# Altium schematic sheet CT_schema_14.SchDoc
size 274 x 160 mm
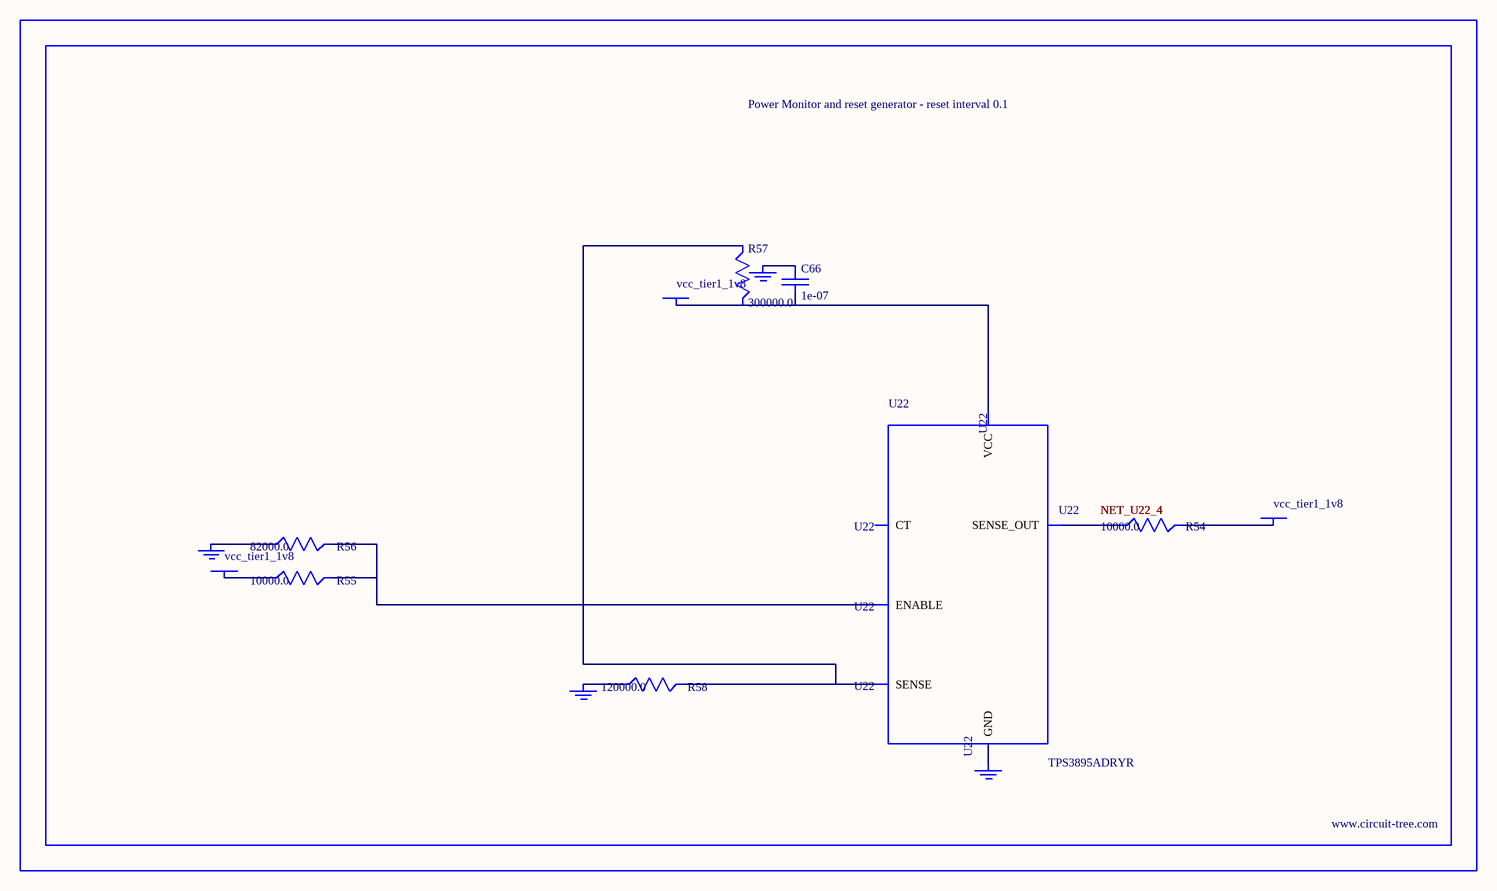
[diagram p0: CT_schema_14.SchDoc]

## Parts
BORDER13  (no value)
C66  1e-07  [C0402]
GND_INSTANCE_13_0  (no value)
GND_INSTANCE_13_1  (no value)
GND_INSTANCE_13_2  (no value)
GND_INSTANCE_13_3  (no value)
POWER_INSTANCE_13_0  vcc_tier1_1v8
POWER_INSTANCE_13_1  vcc_tier1_1v8
POWER_INSTANCE_13_2  vcc_tier1_1v8
R54  10000.0  [R0603]
R55  10000.0  [R0603]
R56  82000.0  [R0603]
R57  300000.0  [R0603]
R58  120000.0  [R0603]
U22  TPS3895ADRYR  [SON-6]

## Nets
NetC66_1: C66.1 GND_INSTANCE_13_2.0(GND)
NetC66_2: C66.2 POWER_INSTANCE_13_2.0(PWR) R57.2 U22.6(VCC)
NetGND_INSTANCE_13_0_0: GND_INSTANCE_13_0.0(GND) R56.1
NetGND_INSTANCE_13_1_0: GND_INSTANCE_13_1.0(GND) R58.1
NetGND_INSTANCE_13_3_0: GND_INSTANCE_13_3.0(GND) U22.2(GND)
NetPOWER_INSTANCE_13_0_0: POWER_INSTANCE_13_0.0(PWR) R55.1
NetPOWER_INSTANCE_13_1_0: POWER_INSTANCE_13_1.0(PWR) R54.2
NetR54_1: R54.1 U22.4(SENSE_OUT)
NetR55_2: R55.2 R56.2 U22.1(ENABLE)
NetR57_1: R57.1 R58.2 U22.3(SENSE)

Not connected (* = marked no-connect by the designer): U22 5(CT)

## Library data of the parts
BORDER13 = BORDER_PAGE13
C66 = C0402C104K3RACTU
GND_INSTANCE_13_0-GND_INSTANCE_13_3 = GND
POWER_INSTANCE_13_0-POWER_INSTANCE_13_2 = PWR
R54 R55 = RC0603JR-0710KL
R56 = RC0603JR-0782KL
R57 = RC0603JR-07300KL
R58 = RC0603JR-07120KL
